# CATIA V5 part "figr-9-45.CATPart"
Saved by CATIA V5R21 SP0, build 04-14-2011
Part number: Part1
Bounding box of the stored display mesh (mm): x -159.661 to 182.627, y -78.048 to 78.048, z 0 to 72.429
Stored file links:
  D:\CATIA V5R21 E-RESOURCES\CATIA-V5R21\catia-v5r21-prt\c09-catia-v5r20-prt\c09-catia-v5r21-figr-9-45.CATPart
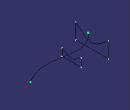
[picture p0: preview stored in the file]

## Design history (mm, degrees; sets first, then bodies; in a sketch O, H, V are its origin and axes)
Body1 (main body)
  Plane1: type Offset, RefPlane yz-plane, Offset 100
  Plane2: type Offset, RefPlane yz-plane, Offset 100, reversed
  Sketch1 on Plane1, origin (100, 0, 0), H (0, 1, 0), V (0, 0, 1)
    point P1 (0, 15.965)
    hyperbola C1
    point P2 (0, 3.0416)
    line L1 (54.8261, 44.8858) -> (54.8261, 0)
    point P5 (54.8261, 0)
    line L2 (-54.8261, 44.8858) -> (-54.8261, 0)
    point P6 (-54.8261, 0)
    line L3 (-54.8261, 0) -> (54.8261, 0)
    coincidence: P1 V, P2 V, P5 H, P6 H
    vertical: L1 V, L2 V
    horizontal: L3 H
  Sketch2 on xy-plane, origin (0, 0, 0), H (1, 0, 0), V (0, 1, 0)
    spline S1 through (-159.6608, -77.1468) (-77.8466, -31.8169) (23.6283, -41.4968) (182.6271, -11.7333)
  Sketch3 on yz-plane, origin (0, 0, 0), H (0, 1, 0), V (0, 0, 1)
    point P1 (0, 18.9787)
    hyperbola C1
    point P2 (0, 2.6681)
    line L1 (48.2237, 37.1764) -> (48.2237, 0)
    point P5 (48.2237, 0)
    line L2 (-43.6563, 34.1546) -> (-43.6563, 0)
    point P6 (-43.6563, 0)
    line L3 (-43.6563, 0) -> (48.2237, 0)
    coincidence: P1 V, P2 V, P5 H, P6 H
    vertical: L1 V, L2 V
    horizontal: L3 H
  Sketch4 on Plane2, origin (-100, 0, 0), H (0, 1, 0), V (0, 0, 1)
    point P1 (0, 140.6052)
    point P2 (0, 41.8972)
    hyperbola C1
    line L1 (78.0478, 72.4293) -> (78.0478, 0)
    point P5 (78.0478, 0)
    line L2 (-78.0478, 72.4293) -> (-78.0478, 0)
    point P6 (-78.0478, 0)
    line L3 (-78.0478, 0) -> (78.0478, 0)
    coincidence: P1 V, P2 V, P5 H, P6 H
    vertical: L1 V, L2 V
    horizontal: L3 H
  Loft1: solid, Spine Sketch2, Sections (Sketch3; Sketch4)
